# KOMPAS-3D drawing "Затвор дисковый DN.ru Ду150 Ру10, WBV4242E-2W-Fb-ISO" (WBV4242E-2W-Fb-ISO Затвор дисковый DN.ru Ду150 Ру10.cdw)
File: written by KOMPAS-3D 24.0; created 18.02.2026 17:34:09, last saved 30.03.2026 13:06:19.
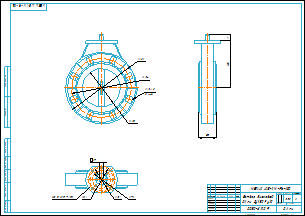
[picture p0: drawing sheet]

Document properties: Автор: R2D2; Форматы листов документа: A2; Полное имя файла: WBV4242E-2W-Fb-ISO Затвор дисковый DN.ru Ду150 Ру10.m3d; Масса: 3.95; Наименование: Затвор дисковый DN.ru Ду150 Ру10; Количество листов документа: 1; Примечание: D050-81209

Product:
- Component [assembly]: Сборка1  | qty 1  | Масса: 0.001636; Автор: R2D2; source file: исходные материалы\dn150_3d_step.a3d
- Part/product: Затвор дисковый DN.ru Ду150 Ру10  | designation WBV4242E-2W-Fb-ISO
    Масса: 3.95
    Раздел спецификации: Прочие изделия
    Примечание: D050-81209

Views: Вид 1, Спереди, Проекционный вид 2, Проекционный вид 3
Referenced files in E:\Работа\Зайцев\WBV4242E-2W-Fb-ISO Затвор дисковый DN.ru Ду50-200 Ру10\DN150\: WBV4242E-2W-Fb-ISO Затвор дисковый DN.ru Ду150 Ру10.m3d
Referenced files in E:\Работа\Зайцев\Для компаса\: чертеж DN.ru А3.cdt
Referenced files in E:\Работа\Зайцев\WBV4242E-2W-Fb-ISO Затвор дисковый DN.ru Ду50-200 Ру10\DN150\исходные материалы\: Деталь1 Деталь1.m3d, Деталь2 Деталь2.m3d, AS 1427 - M3,5 x 5 AS 1427 - M3,5 x 5(5) II.m3d, dn150_3d_step.a3d
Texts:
  WBV4242E-2W-Fb-ISO
  ISO 5211 F07/F10
  чертеж DN.ru А3.cdt
  Затвор дисковый
  DN.ru Ду150 Ру10
  Твердое тело1
  Деталь1
  Деталь1 Деталь1
  Деталь2
  Деталь2 Деталь2
  Solid1
  AS 1427 - M3,5 x 5(5) II
  AS 1427 - M3,5 x 5
  AS 1427 - M3,5 x 5 AS 1427 - M3,5 x 5(5) II
  Сборка1
  Сборка1 Сборка1
  Затвор дисковый DN.ru Ду150 Ру10
  WBV4242E-2W-Fb-ISO Затвор дисковый DN.ru Ду150 Ру10
Dimensions and other numbers on the sheet: 0; 3; 2; 4; 280; 234; 150; 8 отв.; 22; 185; 69; 5; 102; 90; 70; 17; 1:2; 1; 3,95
